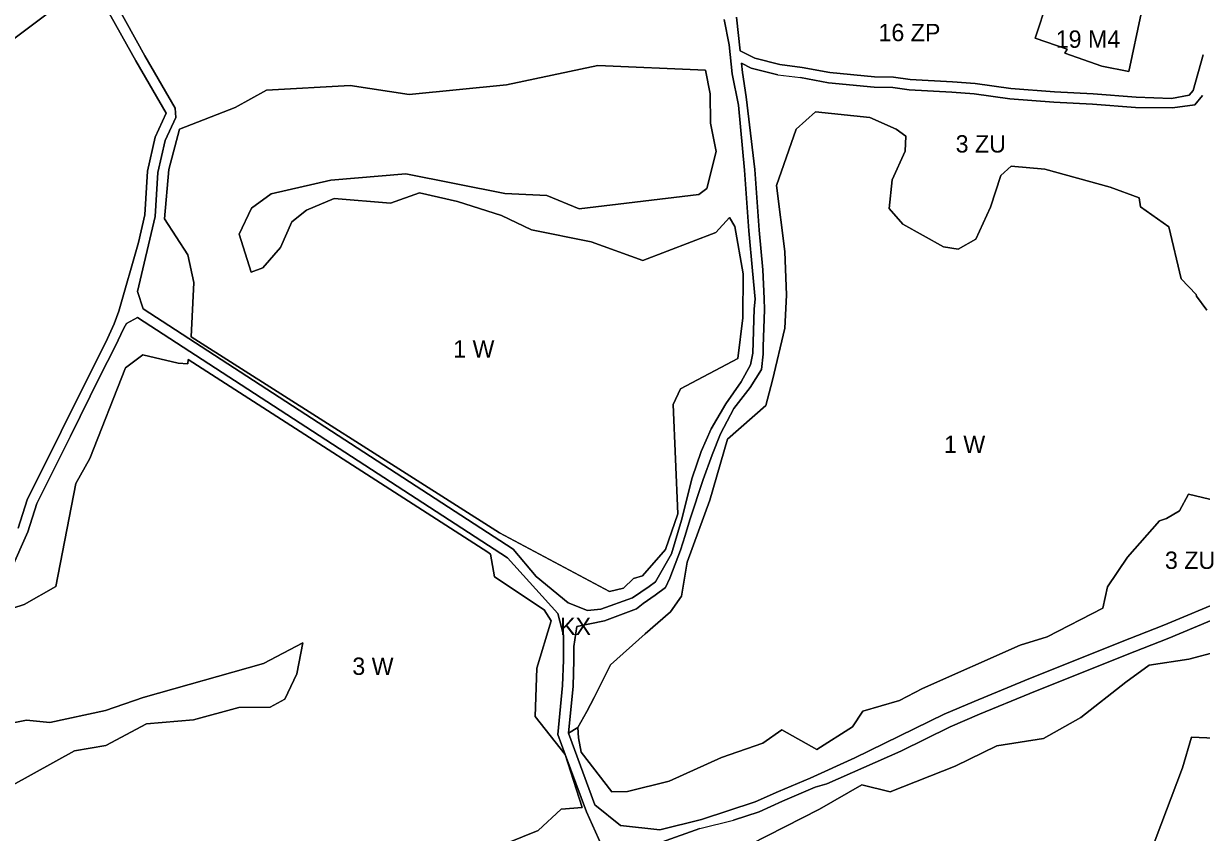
# Model space of a CAD drawing. Extents: x 7437831 to 7440315, y 5545798 to 5547888.
# Drawn here: x 7438706 to 7439385, y 5546523 to 5546989 of the extents above; entities that cross this region are included whole.
import ezdxf

# ---------------------------------------------------------------- set-up
doc = ezdxf.new("R2010")
doc.units = 0
doc.layers.add('linie_rozgraniczajace', color=7, linetype='Continuous')
doc.layers.add('oznaczenia_przeznaczen', color=7, linetype='Continuous')

msp = doc.modelspace()

# ---------------------------------------------------------------- linework, layer by layer
at = {"layer": 'linie_rozgraniczajace'}
for points in [[(7438745.98, 5547014.32), (7438649.6, 5546941.86), (7438616.93, 5546917.59), (7438602.71, 5546903.9), (7438567.13, 5546886.79), (7438479.59, 5546884.81), (7438479.2, 5546912.04), (7438483.68, 5546912.73), (7438509.66, 5546909.77), (7438535.64, 5546906.82), (7438536.32, 5546912.78), (7438481.41, 5546919.46), (7438470.18, 5546947.72), (7438480.26, 5546963.41), (7438496.53, 5546979.31), (7438503.12, 5546983.98), (7438533.91, 5547005.79)], [(7438649.6, 5546941.86), (7438745.98, 5547014.32)], [(7438753.97, 5546997.98), (7438771.06, 5546967.29), (7438788.54, 5546937.15), (7438782.23, 5546923.34), (7438777.79, 5546903.83), (7438776.27, 5546878.52), (7438772.44, 5546862.55), (7438761.22, 5546823.15), (7438758.59, 5546815.79), (7438753.7, 5546805.27), (7438744.99, 5546788.1), (7438728.04, 5546753.68), (7438708.32, 5546714.39), (7438703.18, 5546697.95)], [(7438703.18, 5546697.95), (7438708.32, 5546714.39), (7438728.04, 5546753.68), (7438744.99, 5546788.1), (7438753.7, 5546805.27), (7438758.59, 5546815.79), (7438761.22, 5546823.15), (7438772.44, 5546862.55), (7438776.27, 5546878.52), (7438777.79, 5546903.83), (7438782.23, 5546923.34), (7438788.54, 5546937.15), (7438771.06, 5546967.29), (7438753.97, 5546997.98)], [(7439110.04, 5546991.19), (7439112.9, 5546976.52), (7439114.73, 5546959.82), (7439118.31, 5546941.77), (7439121.74, 5546904.32), (7439124.18, 5546869.34), (7439126.41, 5546846.38), (7439127.92, 5546829.98), (7439127.32, 5546824.31), (7439126.48, 5546798.83), (7439125.21, 5546792.13), (7439119.81, 5546782.23), (7439111.05, 5546769.58), (7439102.59, 5546755.14), (7439096.78, 5546742.23), (7439091.6, 5546726.99), (7439085.4, 5546702.64), (7439079.6, 5546683.16), (7439070.53, 5546667), (7439066.81, 5546664.26), (7439057.21, 5546657.71), (7439039.04, 5546651.35), (7439031.34, 5546650.55), (7439020.12, 5546654.88), (7439001.72, 5546670.1), (7438988.44, 5546685.8), (7438775.21, 5546824.45), (7438771.94, 5546834.31), (7438782.23, 5546877.64), (7438783.75, 5546902.98), (7438787.94, 5546921.41), (7438794, 5546934.65), (7438793.73, 5546940.16), (7438776.27, 5546970.26), (7438759.29, 5547000.75)], [(7438759.29, 5547000.75), (7438776.27, 5546970.26), (7438793.73, 5546940.16), (7438794, 5546934.65), (7438787.94, 5546921.41), (7438783.75, 5546902.98), (7438782.23, 5546877.64), (7438771.94, 5546834.31), (7438775.21, 5546824.45), (7438988.44, 5546685.8), (7439001.72, 5546670.1), (7439020.12, 5546654.88), (7439031.34, 5546650.55), (7439039.04, 5546651.35), (7439057.21, 5546657.71), (7439066.81, 5546664.26), (7439070.53, 5546667), (7439079.6, 5546683.16), (7439085.4, 5546702.64), (7439091.6, 5546726.99), (7439096.78, 5546742.23), (7439102.59, 5546755.14), (7439111.05, 5546769.58), (7439119.81, 5546782.23), (7439125.21, 5546792.13), (7439126.48, 5546798.83), (7439127.32, 5546824.31), (7439127.92, 5546829.98), (7439126.41, 5546846.38), (7439124.18, 5546869.34), (7439121.74, 5546904.32), (7439118.31, 5546941.77), (7439114.73, 5546959.82), (7439112.9, 5546976.52), (7439110.04, 5546991.19)], [(7439350.33, 5546994.61), (7439343.28, 5546961.3), (7439327.75, 5546964.31), (7439306.43, 5546971.85), (7439307.74, 5546974.15), (7439289.28, 5546980.4), (7439296.42, 5547001.93)], [(7439296.42, 5547001.93), (7439289.28, 5546980.4), (7439307.74, 5546974.15), (7439306.43, 5546971.85), (7439327.75, 5546964.31), (7439343.28, 5546961.3), (7439350.33, 5546994.61)], [(7439386.11, 5546970.9), (7439380.33, 5546950.3), (7439377.99, 5546947.51), (7439367.88, 5546945.58), (7439347.49, 5546946.47), (7439322.7, 5546948.4), (7439300.33, 5546949.57), (7439275.26, 5546951.46), (7439254.67, 5546954.31), (7439241.63, 5546955.25), (7439217.29, 5546956.54), (7439207.66, 5546957.99), (7439196.74, 5546958.16), (7439170.89, 5546960.67), (7439154.96, 5546963.6), (7439142.01, 5546965.28), (7439127.77, 5546968.87), (7439119.3, 5546973.15), (7439117.06, 5546992.55)], [(7439117.06, 5546992.55), (7439119.3, 5546973.15), (7439127.77, 5546968.87), (7439142.01, 5546965.28), (7439154.96, 5546963.6), (7439170.89, 5546960.67), (7439196.74, 5546958.16), (7439207.66, 5546957.99), (7439217.29, 5546956.54), (7439241.63, 5546955.25), (7439254.67, 5546954.31), (7439275.26, 5546951.46), (7439300.33, 5546949.57), (7439322.7, 5546948.4), (7439347.49, 5546946.47), (7439367.88, 5546945.58), (7439377.99, 5546947.51), (7439380.33, 5546950.3), (7439386.11, 5546970.9)], [(7439140.89, 5546959.38), (7439125.66, 5546963.22), (7439120.09, 5546966.03), (7439120.67, 5546960.74), (7439122.66, 5546946.63), (7439127.72, 5546904.8), (7439130.16, 5546869.84), (7439132.38, 5546846.95), (7439133.01, 5546830.37), (7439133.31, 5546823.89), (7439132.55, 5546802.61), (7439132.47, 5546798.21), (7439131.51, 5546789.51), (7439124.92, 5546779.08), (7439115.56, 5546766.91), (7439107.93, 5546752.38), (7439103.07, 5546740.19), (7439097.85, 5546725.99), (7439090.19, 5546702.73), (7439087.62, 5546693.66), (7439084.94, 5546685.36), (7439078.8, 5546669.19), (7439076.28, 5546663.78), (7439070.28, 5546659.36), (7439063.31, 5546654.61), (7439059.52, 5546651.5), (7439041.1, 5546644.6), (7439025.14, 5546641.25), (7439023.41, 5546629.75), (7439023.34, 5546621.78), (7439022.93, 5546606.81), (7439020.29, 5546579.76), (7439035.51, 5546538.55), (7439050.28, 5546526.63), (7439072.91, 5546524.01), (7439096.94, 5546529.94), (7439127.96, 5546540.12), (7439141.32, 5546546.07), (7439159.54, 5546553.88), (7439185.3, 5546565.47), (7439236.87, 5546590.73), (7439254.02, 5546598.04), (7439283.2, 5546610.14), (7439338.33, 5546632.23), (7439363.32, 5546641.95), (7439435.2, 5546672.02)], [(7439120.67, 5546960.74), (7439120.09, 5546966.03), (7439125.66, 5546963.22), (7439140.89, 5546959.38), (7439154.03, 5546957.67), (7439170.06, 5546954.73), (7439196.41, 5546952.17), (7439207.17, 5546952), (7439216.68, 5546950.57), (7439241.26, 5546949.26), (7439254.04, 5546948.34), (7439274.63, 5546945.49), (7439299.95, 5546943.59), (7439322.31, 5546942.41), (7439347.12, 5546940.48), (7439368.45, 5546940.26), (7439381.22, 5546942.02), (7439385.76, 5546947.44)], [(7439130.16, 5546869.84), (7439127.72, 5546904.8), (7439122.66, 5546946.63), (7439120.67, 5546960.74)], [(7439385.76, 5546947.44), (7439381.22, 5546942.02), (7439368.45, 5546940.26), (7439347.12, 5546940.48), (7439322.31, 5546942.41), (7439299.95, 5546943.59), (7439274.63, 5546945.49), (7439254.04, 5546948.34), (7439241.26, 5546949.26), (7439216.68, 5546950.57), (7439207.17, 5546952), (7439196.41, 5546952.17), (7439170.06, 5546954.73), (7439154.03, 5546957.67)], [(7439388.08, 5546823.63), (7439382.15, 5546831.69), (7439381.96, 5546832.72), (7439373.46, 5546841.69), (7439366.3, 5546871.69), (7439350.01, 5546883.11), (7439349.23, 5546888.46), (7439332.46, 5546894.52), (7439294.88, 5546904.84), (7439275.39, 5546906.59), (7439269.45, 5546901.22), (7439263.51, 5546882.99), (7439255.03, 5546864.65), (7439244.91, 5546858.78), (7439236.35, 5546860.17), (7439213.05, 5546873.26), (7439205.07, 5546882.28), (7439206.83, 5546898.82), (7439214.36, 5546915.23), (7439214.63, 5546923.93), (7439209.06, 5546927.99), (7439193.91, 5546934.61), (7439162.63, 5546937.98), (7439151.58, 5546928.02), (7439140.22, 5546895.41), (7439144.9, 5546857.53), (7439146.02, 5546832.22), (7439145.06, 5546813.3), (7439137.96, 5546783.25), (7439133.97, 5546768.67), (7439112, 5546749.32), (7439101.69, 5546714.19), (7439088.63, 5546678.34), (7439085.43, 5546658.72), (7439079.14, 5546649.69), (7439064.47, 5546637), (7439044.58, 5546619.26), (7439035.14, 5546600.26), (7439030.98, 5546592.26), (7439025.61, 5546583.02), (7439020.29, 5546579.76), (7439022.93, 5546606.81), (7439023.34, 5546621.78), (7439023.41, 5546629.75), (7439025.14, 5546641.25), (7439041.1, 5546644.6), (7439059.52, 5546651.5), (7439063.31, 5546654.61), (7439070.28, 5546659.36), (7439076.28, 5546663.78), (7439078.8, 5546669.19), (7439084.94, 5546685.36), (7439087.62, 5546693.66), (7439090.19, 5546702.73), (7439097.85, 5546725.99), (7439103.07, 5546740.19), (7439107.93, 5546752.38), (7439115.56, 5546766.91), (7439124.92, 5546779.08), (7439131.51, 5546789.51), (7439132.47, 5546798.21), (7439132.55, 5546802.61), (7439133.31, 5546823.89), (7439133.01, 5546830.37), (7439132.38, 5546846.95), (7439130.16, 5546869.84)], [(7439401.89, 5546711.77), (7439377.63, 5546717.6), (7439372.39, 5546708.01), (7439364.84, 5546703.46), (7439360.94, 5546702.19), (7439342.44, 5546681.27), (7439330.85, 5546664.2), (7439328.15, 5546651.92), (7439296.08, 5546635.33), (7439280.67, 5546630.54), (7439224.31, 5546605.46), (7439211, 5546598.69), (7439189.92, 5546592.54), (7439183.91, 5546583.53), (7439163.47, 5546570.41), (7439143.33, 5546581.7), (7439132.33, 5546573.98), (7439108.44, 5546565.79), (7439078.26, 5546552.13), (7439054.41, 5546546.12), (7439045.3, 5546545.98), (7439027.68, 5546568.86), (7439026.1, 5546577.12), (7439025.61, 5546583.02), (7439030.98, 5546592.26), (7439035.14, 5546600.26), (7439044.58, 5546619.26), (7439064.47, 5546637), (7439079.14, 5546649.69), (7439085.43, 5546658.72), (7439088.63, 5546678.34), (7439101.69, 5546714.19), (7439112, 5546749.32), (7439133.97, 5546768.67), (7439137.96, 5546783.25), (7439145.06, 5546813.3), (7439146.02, 5546832.22), (7439144.9, 5546857.53), (7439140.22, 5546895.41), (7439151.58, 5546928.02), (7439162.63, 5546937.98), (7439193.91, 5546934.61), (7439209.06, 5546927.99), (7439214.63, 5546923.93), (7439214.36, 5546915.23), (7439206.83, 5546898.82), (7439205.07, 5546882.28), (7439213.05, 5546873.26), (7439236.35, 5546860.17), (7439244.91, 5546858.78), (7439255.03, 5546864.65), (7439263.51, 5546882.99), (7439269.45, 5546901.22), (7439275.39, 5546906.59), (7439294.88, 5546904.84), (7439332.46, 5546894.52), (7439349.23, 5546888.46), (7439350.01, 5546883.11), (7439366.3, 5546871.69), (7439373.46, 5546841.69), (7439381.96, 5546832.72), (7439382.15, 5546831.69), (7439388.08, 5546823.63)], [(7438699.06, 5546673.83), (7438708.8, 5546695.84), (7438713.9, 5546712.14), (7438733.41, 5546751.01), (7438750.34, 5546785.38), (7438759.15, 5546802.74), (7438764.03, 5546813.26), (7438765.56, 5546815.87), (7438771.94, 5546819.42), (7438985.17, 5546680.77), (7439014.11, 5546648.75), (7439017.47, 5546636.36), (7439017.35, 5546621.89), (7439016.94, 5546607.19), (7439014.18, 5546578.97), (7439018.45, 5546567.43), (7439030.64, 5546534.44), (7439041.15, 5546511.43), (7438943, 5546472.84), (7438886.32, 5546445.62), (7438832.51, 5546427.97), (7438795.44, 5546418.73), (7438685.57, 5546390.27)], [(7438685.57, 5546390.27), (7438795.44, 5546418.73), (7438832.51, 5546427.97), (7438886.32, 5546445.62), (7438943, 5546472.84), (7439041.15, 5546511.43), (7439030.64, 5546534.44), (7439018.45, 5546567.43), (7439014.18, 5546578.97), (7439016.94, 5546607.19), (7439017.35, 5546621.89), (7439017.47, 5546636.36), (7439014.11, 5546648.75), (7438985.17, 5546680.77), (7438771.94, 5546819.42), (7438765.56, 5546815.87), (7438764.03, 5546813.26), (7438759.15, 5546802.74), (7438750.34, 5546785.38), (7438733.41, 5546751.01), (7438713.9, 5546712.14), (7438708.8, 5546695.84), (7438699.06, 5546673.83)], [(7438933.42, 5546495.59), (7439002.86, 5546523.66), (7439016.11, 5546535.98), (7439028.11, 5546537.03), (7439018.45, 5546567.43), (7439001.08, 5546589.37), (7439002.07, 5546617.31), (7439010.34, 5546644.6), (7439006.21, 5546650.82), (7438977.6, 5546669.89), (7438975.35, 5546683.04), (7438973.89, 5546684.1), (7438801.22, 5546795.16), (7438801.02, 5546792.63), (7438795.38, 5546793.05), (7438774.94, 5546797.82), (7438765.11, 5546790.37), (7438744.46, 5546738.14), (7438736.37, 5546723.77), (7438724.86, 5546664.36), (7438706.64, 5546654.04), (7438686.36, 5546647.35)], [(7438686.36, 5546647.35), (7438706.64, 5546654.04), (7438724.86, 5546664.36), (7438736.37, 5546723.77), (7438744.46, 5546738.14), (7438765.11, 5546790.37), (7438774.94, 5546797.82), (7438795.38, 5546793.05), (7438801.02, 5546792.63), (7438801.22, 5546795.16), (7438973.89, 5546684.1), (7438975.35, 5546683.04), (7438977.6, 5546669.89), (7439006.21, 5546650.82), (7439010.34, 5546644.6), (7439002.07, 5546617.31), (7439001.08, 5546589.37), (7439018.45, 5546567.43), (7439028.11, 5546537.03), (7439016.11, 5546535.98), (7439002.86, 5546523.66), (7438933.42, 5546495.59)], [(7439435.2, 5546672.02), (7439363.32, 5546641.95), (7439338.33, 5546632.23), (7439283.2, 5546610.14), (7439254.02, 5546598.04), (7439236.87, 5546590.73), (7439185.3, 5546565.47), (7439159.54, 5546553.88), (7439141.32, 5546546.07), (7439127.96, 5546540.12), (7439096.94, 5546529.94), (7439072.91, 5546524.01), (7439050.28, 5546526.63), (7439035.51, 5546538.55), (7439020.29, 5546579.76), (7439025.61, 5546583.02), (7439026.1, 5546577.12), (7439027.68, 5546568.86), (7439045.3, 5546545.98), (7439054.41, 5546546.12), (7439078.26, 5546552.13), (7439108.44, 5546565.79), (7439132.33, 5546573.98), (7439143.33, 5546581.7), (7439163.47, 5546570.41), (7439183.91, 5546583.53), (7439189.92, 5546592.54), (7439211, 5546598.69), (7439224.31, 5546605.46), (7439280.67, 5546630.54), (7439296.08, 5546635.33), (7439328.15, 5546651.92), (7439330.85, 5546664.2), (7439342.44, 5546681.27), (7439360.94, 5546702.19), (7439364.84, 5546703.46), (7439372.39, 5546708.01), (7439377.63, 5546717.6), (7439401.89, 5546711.77)], [(7439049.23, 5546508.17), (7439095.95, 5546524.77), (7439115.47, 5546529.65), (7439130.13, 5546534.52), (7439143.72, 5546540.57), (7439162.39, 5546548.58), (7439169.15, 5546550.65), (7439211.74, 5546569.48), (7439240.21, 5546583.45), (7439257.12, 5546590.66), (7439286.22, 5546602.73), (7439341.27, 5546624.79), (7439366.32, 5546634.53), (7439438.35, 5546664.67)], [(7439438.35, 5546664.67), (7439366.32, 5546634.53), (7439341.27, 5546624.79), (7439286.22, 5546602.73), (7439257.12, 5546590.66), (7439240.21, 5546583.45), (7439211.74, 5546569.48), (7439169.15, 5546550.65), (7439162.39, 5546548.58), (7439143.72, 5546540.57), (7439130.13, 5546534.52), (7439115.47, 5546529.65)], [(7438648.07, 5546575.31), (7438708.08, 5546587.26), (7438721.48, 5546585.91), (7438753.5, 5546592.93), (7438775.15, 5546600.43), (7438844.62, 5546620.02), (7438867.32, 5546631.84), (7438863.84, 5546613.96), (7438856.82, 5546599.37), (7438848.47, 5546594.86), (7438830.35, 5546594.49), (7438804.14, 5546587.54), (7438777.06, 5546585.18), (7438753.7, 5546572.62), (7438735.57, 5546569.53), (7438699.95, 5546549.81)], [(7438699.95, 5546549.81), (7438735.57, 5546569.53), (7438753.7, 5546572.62), (7438777.06, 5546585.18), (7438804.14, 5546587.54), (7438830.35, 5546594.49), (7438848.47, 5546594.86), (7438856.82, 5546599.37), (7438863.84, 5546613.96), (7438867.32, 5546631.84), (7438844.62, 5546620.02), (7438775.15, 5546600.43), (7438753.5, 5546592.93), (7438721.48, 5546585.91), (7438708.08, 5546587.26), (7438648.07, 5546575.31)], [(7439393.73, 5546626.76), (7439377.82, 5546622.48), (7439354.99, 5546619.01), (7439341.56, 5546609.11), (7439315.64, 5546588.87), (7439294.09, 5546576.76), (7439267.07, 5546572.41), (7439243.05, 5546560.82), (7439205.64, 5546545.97), (7439189.3, 5546550.04), (7439164.87, 5546535.91), (7439125.09, 5546515.56)], [(7439125.09, 5546515.56), (7439164.87, 5546535.91), (7439189.3, 5546550.04), (7439205.64, 5546545.97), (7439243.05, 5546560.82), (7439267.07, 5546572.41), (7439294.09, 5546576.76), (7439315.64, 5546588.87), (7439341.56, 5546609.11), (7439354.99, 5546619.01), (7439377.82, 5546622.48), (7439393.73, 5546626.76)], [(7439401.45, 5546576.44), (7439379.25, 5546577.57), (7439374.12, 5546559.74), (7439358.43, 5546518.01), (7439338.09, 5546489.26), (7439317.74, 5546466.42), (7439300.33, 5546464.03), (7439283.42, 5546471.79), (7439280.22, 5546468.33), (7439281.31, 5546459.59), (7439272.68, 5546442.36), (7439266.36, 5546408.09), (7439253.82, 5546380.88), (7439248.46, 5546360.85)], [(7439358.43, 5546518.01), (7439374.12, 5546559.74), (7439379.25, 5546577.57), (7439401.45, 5546576.44)], [(7439095.95, 5546524.77), (7439049.23, 5546508.17)]]:
    msp.add_lwpolyline(points, dxfattribs=at)
for points in [[(7439084.91, 5546778.32), (7439117.82, 5546795.81), (7439120.81, 5546819.17), (7439120.96, 5546844.64), (7439116.14, 5546871.82), (7439113.02, 5546877.08), (7439105.14, 5546868.34), (7439063.1, 5546852.2), (7439033.34, 5546863.09), (7438999, 5546869.94), (7438981.65, 5546878.23), (7438956.31, 5546886.28), (7438934.42, 5546891.23), (7438917.71, 5546885.28), (7438885.31, 5546888.05), (7438869.31, 5546881.23), (7438860.92, 5546874.62), (7438854.38, 5546859.8), (7438844.16, 5546848.12), (7438837.4, 5546845.55), (7438830.58, 5546867.47), (7438837.56, 5546882.38), (7438849.08, 5546890.75), (7438883.31, 5546898.57), (7438926.63, 5546902.16), (7438983.62, 5546890.88), (7439007.87, 5546889.74), (7439026.44, 5546882), (7439095.52, 5546890.32), (7439100.06, 5546893.69), (7439105.34, 5546915.14), (7439102.14, 5546931.37), (7439101.87, 5546948.35), (7439099.19, 5546962.04), (7439037.18, 5546964.62), (7438984.56, 5546953.57), (7438928.53, 5546947.9), (7438894.48, 5546953.1), (7438846.39, 5546950.51), (7438828.33, 5546940.43), (7438796.15, 5546927.93), (7438790.08, 5546904.75), (7438787.52, 5546876.25), (7438800.89, 5546855.57), (7438804.49, 5546839.63), (7438802.97, 5546808.28), (7438980.52, 5546695.21), (7439044.04, 5546661.47), (7439051.93, 5546663.47), (7439057.8, 5546668.95), (7439062.99, 5546670.42), (7439076.23, 5546685.66), (7439083.37, 5546706.32), (7439080.7, 5546769.21)], [(7439084.91, 5546778.32), (7439080.7, 5546769.21), (7439083.37, 5546706.32), (7439076.23, 5546685.66), (7439062.99, 5546670.42), (7439057.8, 5546668.95), (7439051.93, 5546663.47), (7439044.04, 5546661.47), (7438980.52, 5546695.21), (7438802.97, 5546808.28), (7438804.49, 5546839.63), (7438800.89, 5546855.57), (7438787.52, 5546876.25), (7438790.08, 5546904.75), (7438796.15, 5546927.93), (7438828.33, 5546940.43), (7438846.39, 5546950.51), (7438894.48, 5546953.1), (7438928.53, 5546947.9), (7438984.56, 5546953.57), (7439037.18, 5546964.62), (7439099.19, 5546962.04), (7439101.87, 5546948.35), (7439102.14, 5546931.37), (7439105.34, 5546915.14), (7439100.06, 5546893.69), (7439095.52, 5546890.32), (7439026.44, 5546882), (7439007.87, 5546889.74), (7438983.62, 5546890.88), (7438926.63, 5546902.16), (7438883.31, 5546898.57), (7438849.08, 5546890.75), (7438837.56, 5546882.38), (7438830.58, 5546867.47), (7438837.4, 5546845.55), (7438844.16, 5546848.12), (7438854.38, 5546859.8), (7438860.92, 5546874.62), (7438869.31, 5546881.23), (7438885.31, 5546888.05), (7438917.71, 5546885.28), (7438934.42, 5546891.23), (7438956.31, 5546886.28), (7438981.65, 5546878.23), (7438999, 5546869.94), (7439033.34, 5546863.09), (7439063.1, 5546852.2), (7439105.14, 5546868.34), (7439113.02, 5546877.08), (7439116.14, 5546871.82), (7439120.96, 5546844.64), (7439120.81, 5546819.17), (7439117.82, 5546795.81)]]:
    msp.add_lwpolyline(points, close=True, dxfattribs=at)

# ---------------------------------------------------------------- texts
at = {"layer": 'oznaczenia_przeznaczen'}
for s, p in [('16 ZP', (7439198.9583, 5546978.7)), ('19 M4', (7439301.0905, 5546974.88)), ('3 ZU', (7439243.4153, 5546914.51)), ('1 W', (7438953.8743, 5546796.34)), ('1 W', (7439236.6943, 5546741.3)), ('3 ZU', (7439364.0253, 5546674.47)), ('KX', (7439015.4736, 5546636.31)), ('3 W', (7438895.7443, 5546613.38))]:
    msp.add_text(s, height=10, dxfattribs=at).set_placement(p)

doc.saveas('drawing.dxf')
